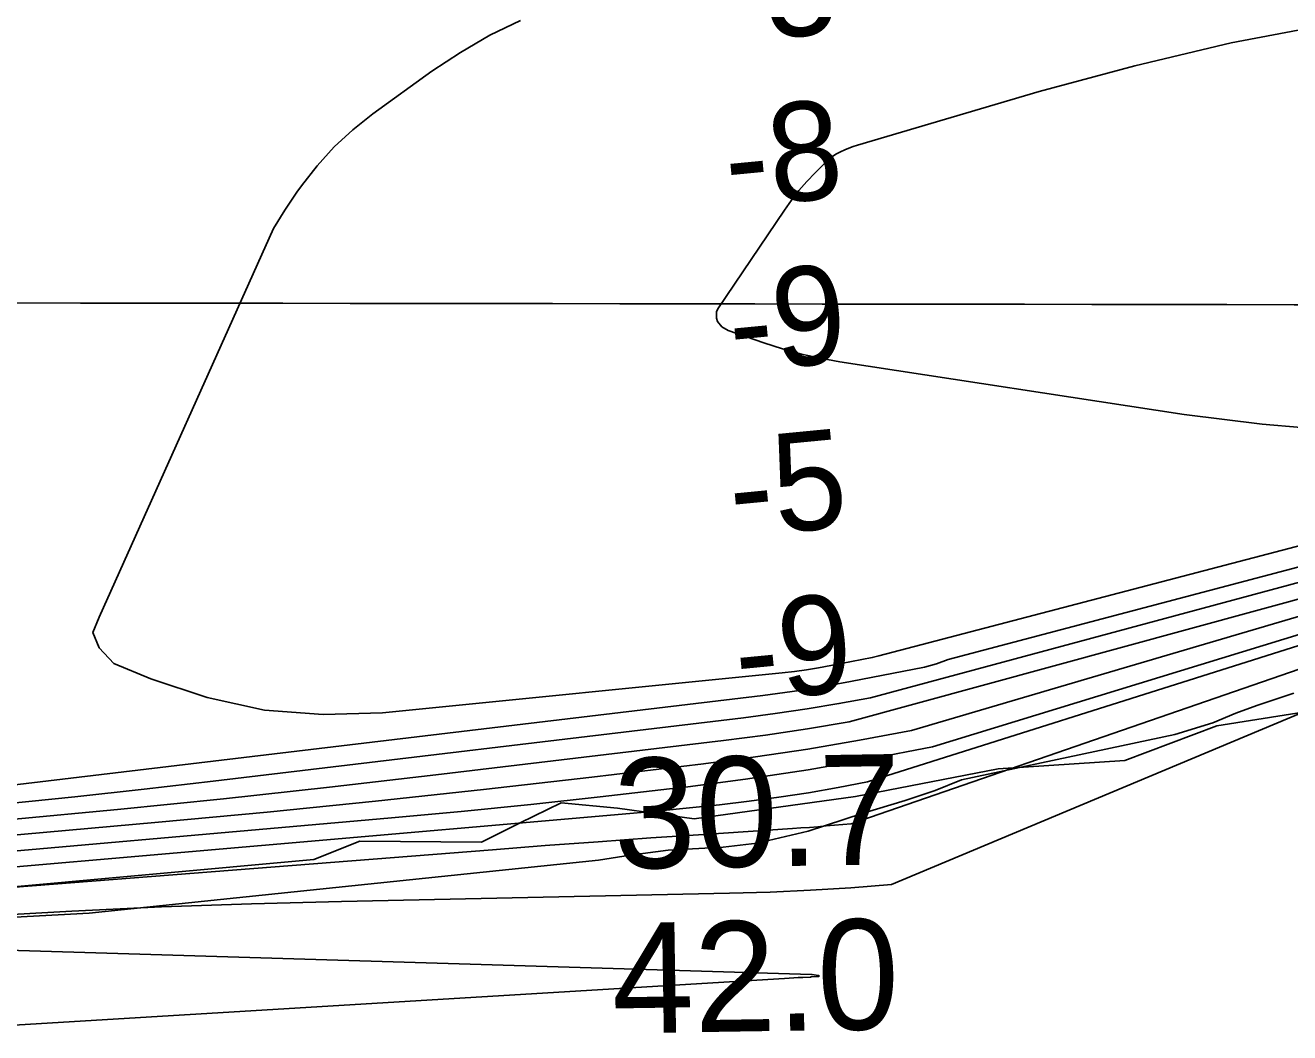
# Model space of a CAD drawing. Extents: x 3219052 to 3256913, y 800770 to 826146.
# Drawn here: x 3230928 to 3231695, y 811791 to 812403 of the extents above; entities that cross this region are included whole.
import ezdxf

# ---------------------------------------------------------------- set-up
doc = ezdxf.new("R2010")
doc.units = 0
for name, color, linetype in [('V-GRID-MAJR', 7, 'Continuous'), ('V-RIVR-EDGE', 7, 'Continuous'), ('V-RIVR-RANG', 7, 'Continuous'), ('V-SITE-VEGE', 7, 'Continuous'), ('V-TOPO-DPTH', 7, 'Continuous'), ('V-TOPO-MAJR', 7, 'Continuous'), ('V-TOPO-MINR', 7, 'Continuous'), ('V-TOPO-WATR', 7, 'Continuous')]:
    doc.layers.add(name, color=color, linetype=linetype)

msp = doc.modelspace()

# ---------------------------------------------------------------- linework, layer by layer
at = {"layer": 'V-GRID-MAJR'}
msp.add_spline([(3223229.222, 812245.659), (3228465.955, 812237.661), (3233702.6890000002, 812230.425), (3238939.4250000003, 812223.951), (3244176.161, 812218.238), (3249412.899, 812213.287), (3254649.637, 812209.098), (3254649.6380000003, 812209.098)], degree=3, dxfattribs=at)
at = {"layer": 'V-RIVR-EDGE'}
msp.add_lwpolyline([(3230903.1019634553, 811878.0231763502), (3231103.0993838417, 811896.2198451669), (3231130.9466271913, 811907.4526457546), (3231204.8405620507, 811906.8352481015), (3231228.3421149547, 811918.5134735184), (3231253.1487722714, 811930.6231509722), (3231287.4806941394, 811927.4955036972), (3231333.9749601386, 811920.8603489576), (3231431.8115734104, 811934.5281610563), (3231518.354120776, 811951.2666544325), (3231595.304764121, 811956.2925278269), (3231650.996026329, 811977.4540994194), (3231716.223301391, 811987.7251115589)], dxfattribs=at)
at = {"layer": 'V-SITE-VEGE'}
for points in [[(3231351.543, 811903.647), (3231372.062, 811906.103), (3231403.021, 811913.412), (3231435.812, 811924.207), (3231461.94, 811932.0530000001), (3231480.108, 811938.074), (3231496.0870000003, 811944.5800000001), (3231625.6180000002, 811972.167), (3231648.648, 811979.194), (3231662.632, 811985.077), (3231675.27, 811989.669), (3231697.87, 811997.1460000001)], [(3230902.756, 811860.164), (3230966.879, 811863.733), (3231275.892, 811895.9010000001), (3231295.1, 811898.824), (3231318.052, 811901.89), (3231351.543, 811903.647)]]:
    msp.add_lwpolyline(points, dxfattribs=at)
at = {"layer": 'V-TOPO-DPTH'}
for points in [[(3231228.470283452, 812405.5174824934), (3231209.8754390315, 812396.6128912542), (3231192.0775494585, 812386.2063975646), (3231174.810963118, 812374.7986355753), (3231138.9305299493, 812348.9006319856), (3231126.8381560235, 812339.2345024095), (3231115.4585998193, 812328.859579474), (3231105.148270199, 812317.4214664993), (3231095.550758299, 812305.2745601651), (3231092.795754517, 812301.4117371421), (3231085.4584558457, 812290.4593476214), (3231078.5657916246, 812279.2511318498), (3230972.842580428, 812043.4696653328), (3230969.0998905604, 812034.0702753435), (3230972.873749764, 812024.6833564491), (3230981.658641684, 812015.3047516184), (3231004.2032776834, 812005.9615947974), (3231038.455751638, 811994.6830115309), (3231073.2217979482, 811986.8883609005), (3231108.7582027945, 811984.3196092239), (3231144.808179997, 811985.2347901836), (3231387.3178908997, 812009.608056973), (3231394.7129821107, 812010.4547092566), (3231402.0880969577, 812011.436995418), (3231409.433247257, 812012.622732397), (3231416.7584211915, 812013.9441032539), (3231441.950385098, 812018.8489342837), (3231445.9223999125, 812019.9308635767), (3231982.116089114, 812160.2718226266)], [(3231228.470283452, 812405.5174824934), (3231209.8754390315, 812396.6128912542), (3231192.0775494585, 812386.2063975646), (3231174.810963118, 812374.7986355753), (3231138.9305299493, 812348.9006319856), (3231126.8381560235, 812339.2345024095), (3231115.4585998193, 812328.859579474), (3231105.148270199, 812317.4214664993), (3231095.550758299, 812305.2745601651), (3231092.795754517, 812301.4117371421), (3231085.4584558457, 812290.4593476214), (3231078.5657916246, 812279.2511318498), (3230972.842580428, 812043.4696653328), (3230969.0998905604, 812034.0702753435), (3230972.873749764, 812024.6833564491), (3230981.658641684, 812015.3047516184), (3231004.2032776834, 812005.9615947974), (3231038.455751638, 811994.6830115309), (3231073.2217979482, 811986.8883609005), (3231108.7582027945, 811984.3196092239), (3231144.808179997, 811985.2347901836), (3231387.3178908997, 812009.608056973), (3231394.7129821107, 812010.4547092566), (3231402.0880969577, 812011.436995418), (3231409.433247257, 812012.622732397), (3231416.7584211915, 812013.9441032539), (3231441.950385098, 812018.8489342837), (3231445.9223999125, 812019.9308635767), (3231982.116089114, 812160.2718226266)], [(3233098.349688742, 812373.6540765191), (3232486.2368681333, 812270.0368842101), (3232472.3644264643, 812267.6833421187), (3232458.5200075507, 812265.1815515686), (3232444.7176227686, 812262.45738833), (3232430.9432607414, 812259.5849766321), (3232002.2757216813, 812145.8369136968), (3231440.9252670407, 811994.4826974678), (3231421.714519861, 811990.9133475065), (3231402.457251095, 811987.6377519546), (3231383.130199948, 811984.8027880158), (3231363.7566272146, 811982.2615784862), (3231042.0572564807, 811943.7967718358), (3231000.117694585, 811938.9610847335), (3230958.1533135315, 811934.360955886), (3230916.1517037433, 811930.1141644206)], [(3230916.1517037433, 811930.1141644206), (3230958.1533135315, 811934.360955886), (3231000.117694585, 811938.9610847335), (3231042.0572564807, 811943.7967718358), (3231363.7566272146, 811982.2615784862), (3231383.130199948, 811984.8027880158), (3231402.457251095, 811987.6377519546), (3231421.714519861, 811990.9133475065), (3231440.9252670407, 811994.4826974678), (3232002.2757216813, 812145.8369136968), (3232430.9432607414, 812259.5849766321), (3232444.7176227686, 812262.45738833), (3232458.5200075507, 812265.1815515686), (3232472.3644264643, 812267.6833421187), (3232486.2368681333, 812270.0368842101), (3233098.349688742, 812373.6540765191)], [(3233156.239928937, 812345.4144281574), (3232562.990278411, 812238.0299150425), (3232553.054541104, 812236.3939197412), (3232543.109941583, 812234.815359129), (3232533.15204874, 812233.3229505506), (3232523.1852936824, 812231.8879766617), (3232513.230339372, 812230.3910913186), (3232503.2999576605, 812228.7543577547), (3232493.4064348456, 812226.90785186), (3232483.537484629, 812224.9214977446), (3232479.2659793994, 812224.0146192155), (3232467.289212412, 812221.4275986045), (3231967.5589998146, 812122.4509561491), (3231465.7381548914, 811974.6738844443), (3231434.3190708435, 811968.7257062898), (3231402.819035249, 811963.2818956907), (3231371.1975723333, 811958.5946364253), (3231339.4951578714, 811954.4117447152), (3231271.806260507, 811946.3050010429), (3231206.167293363, 811938.7475382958), (3231140.4865882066, 811931.5900274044), (3231074.743276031, 811925.0324442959), (3231008.958225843, 811918.8748130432), (3230827.9939512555, 811902.769120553)]]:
    msp.add_lwpolyline(points, dxfattribs=at)
at = {"layer": 'V-TOPO-MAJR'}
msp.add_lwpolyline([(3230859.4972477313, 811874.5255959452), (3231211.463408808, 811902.2274491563), (3231243.5132287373, 811904.6882806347), (3231275.5689604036, 811907.0673374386), (3231307.633559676, 811909.3237322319), (3231339.704070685, 811911.4983523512), (3231393.599473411, 811915.0493001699), (3231398.7255397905, 811915.4026005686), (3231403.850036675, 811915.7765489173), (3231408.9721793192, 811916.1814691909), (3231414.092752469, 811916.6070374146), (3231429.257659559, 811917.9135520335), (3231899.6914986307, 812080.3429716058)], dxfattribs=at)
at = {"layer": 'V-TOPO-MINR'}
for points in [[(3231228.470283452, 812405.5174824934), (3231209.8754390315, 812396.6128912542), (3231192.0775494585, 812386.2063975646), (3231174.810963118, 812374.7986355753), (3231138.9305299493, 812348.9006319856), (3231126.8381560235, 812339.2345024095), (3231115.4585998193, 812328.859579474), (3231105.148270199, 812317.4214664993), (3231095.550758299, 812305.2745601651), (3231092.795754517, 812301.4117371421), (3231085.4584558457, 812290.4593476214), (3231078.5657916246, 812279.2511318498), (3230972.842580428, 812043.4696653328), (3230969.0998905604, 812034.0702753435), (3230972.873749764, 812024.6833564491), (3230981.658641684, 812015.3047516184), (3231004.2032776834, 812005.9615947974), (3231038.455751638, 811994.6830115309), (3231073.2217979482, 811986.8883609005), (3231108.7582027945, 811984.3196092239), (3231144.808179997, 811985.2347901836), (3231387.3178908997, 812009.608056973), (3231394.7129821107, 812010.4547092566), (3231402.0880969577, 812011.436995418), (3231409.433247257, 812012.622732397), (3231416.7584211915, 812013.9441032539), (3231441.950385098, 812018.8489342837), (3231445.9223999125, 812019.9308635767), (3231982.116089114, 812160.2718226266)], [(3231718.7033630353, 812403.1763464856), (3231659.701011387, 812391.9968638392), (3231601.273605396, 812378.1225508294), (3231543.2294965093, 812362.4516842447), (3231433.0033608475, 812329.9596546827), (3231430.38679653, 812329.1151355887), (3231427.8041605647, 812328.1835796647), (3231425.2724171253, 812327.1214684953), (3231422.7746020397, 812325.9723204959), (3231420.3811386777, 812324.6469930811), (3231418.0903942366, 812323.1775266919), (3231415.9537281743, 812321.4918518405), (3231413.9197810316, 812319.6620380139), (3231407.3636469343, 812313.155780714), (3231402.299349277, 812307.8227287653), (3231397.4585169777, 812302.3050451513), (3231392.952882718, 812296.5104140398), (3231388.6707138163, 812290.5311512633), (3231348.361560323, 812230.5666397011), (3231347.5272323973, 812228.6839642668), (3231347.376836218, 812224.8589172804), (3231348.0607679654, 812222.9165457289), (3231350.794592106, 812219.6260277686), (3231354.5123948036, 812217.5096048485), (3231376.1061868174, 812209.9317489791), (3231387.488627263, 812206.2909091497), (3231398.9784752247, 812203.0804262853), (3231410.629434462, 812200.5154788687), (3231422.3878012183, 812198.3808884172), (3231631.2095695, 812166.4655886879), (3231678.5091910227, 812160.6020928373), (3231725.911758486, 812156.5301610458)], [(3230909.7779353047, 811940.1000302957), (3231375.6213572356, 811995.8697754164), (3231388.9645777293, 811997.6184653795), (3231402.276629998, 811999.5648836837), (3231415.541929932, 812001.8078944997), (3231428.77606164, 812004.2486336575), (3231473.592392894, 812013.0323078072), (3231480.9644786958, 812015.0252567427), (3231488.0453462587, 812017.6596658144), (3232013.5471657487, 812156.589880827), (3232045.6238793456, 812162.8151654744), (3232436.2519301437, 812280.2505831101), (3232459.941382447, 812285.0879870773), (3232483.706498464, 812289.5388171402), (3232507.5220569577, 812293.7319312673), (3232584.6246720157, 812306.660394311), (3233085.958948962, 812387.211552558)], [(3230919.4482350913, 811920.5737085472), (3230983.92161747, 811926.6673520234), (3231048.3556352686, 811933.136541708), (3231112.7306061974, 811940.169050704), (3231177.066212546, 811947.577105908), (3231351.7311122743, 811968.4636540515), (3231377.2160688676, 811971.8138223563), (3231402.6380203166, 811975.5594926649), (3231427.965464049, 811979.8984159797), (3231964.852140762, 812126.4828974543), (3232416.4774682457, 812236.7248742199), (3232423.5506967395, 812238.8422121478), (3232430.7014445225, 812240.6808223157), (3232437.9038718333, 812242.3336139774), (3232448.4340848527, 812244.5336939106), (3232452.7988938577, 812245.4096572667), (3232457.1720889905, 812246.2394308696), (3232461.557863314, 812246.9999198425), (3232465.9520237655, 812247.7142190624), (3233157.50439058, 812360.4364484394)], [(3230827.9939512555, 811902.769120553), (3231008.958225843, 811918.8748130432), (3231074.743276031, 811925.0324442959), (3231140.4865882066, 811931.5900274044), (3231206.167293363, 811938.7475382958), (3231271.806260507, 811946.3050010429), (3231339.4951578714, 811954.4117447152), (3231371.1975723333, 811958.5946364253), (3231402.819035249, 811963.2818956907), (3231434.3190708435, 811968.7257062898), (3231465.7381548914, 811974.6738844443), (3231967.5589998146, 812122.4509561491), (3232467.289212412, 812221.4275986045), (3232479.2659793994, 812224.0146192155), (3232483.537484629, 812224.9214977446), (3232493.4064348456, 812226.90785186), (3232503.2999576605, 812228.7543577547), (3232513.230339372, 812230.3910913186), (3232523.1852936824, 812231.8879766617), (3232533.15204874, 812233.3229505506), (3232543.109941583, 812234.815359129), (3232553.054541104, 812236.3939197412), (3232562.990278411, 812238.0299150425), (3233156.239928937, 812345.4144281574)], [(3230837.8612534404, 811894.0736250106), (3231150.298528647, 811921.5222196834), (3231192.530069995, 811925.4368195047), (3231234.7335255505, 811929.6214623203), (3231276.8948524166, 811934.2111696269), (3231319.0280934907, 811939.0709199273), (3231326.9945756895, 811940.02857483), (3231365.047873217, 811945.0788177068), (3231403.0004671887, 811950.7505149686), (3231440.802005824, 811957.3543938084), (3231478.5028409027, 811964.5797270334), (3231952.4298236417, 812110.0529328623), (3232115.7254834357, 812133.6460863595), (3232172.2098851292, 812142.1591000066), (3232228.6185235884, 812151.1304446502), (3232400.1222106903, 812181.8940793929), (3232426.813538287, 812186.7205580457), (3232453.5364188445, 812191.359418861), (3232480.306628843, 812195.7168529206), (3232507.1083918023, 812199.8866691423), (3232543.7690222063, 812205.3929408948), (3232568.7269474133, 812209.2154199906), (3233147.483664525, 812329.3229014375)], [(3230847.7329094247, 811885.3534478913), (3231294.9250262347, 811924.1199622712), (3231313.052071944, 811925.7842809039), (3231331.1663779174, 811927.5713430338), (3231349.261574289, 811929.5425204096), (3231367.3440309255, 811931.636441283), (3231385.379596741, 811934.0500581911), (3231403.365458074, 811936.7667134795), (3231421.2767626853, 811939.9379263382), (3231439.138362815, 811943.4121775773), (3231915.2320351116, 812093.9400519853), (3231928.4322151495, 812095.8886727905), (3231941.6378416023, 812097.8009196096), (3232201.8475326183, 812134.9316493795), (3232243.577777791, 812140.9298019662), (3232285.2997304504, 812146.9846879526), (3232327.0092443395, 812153.1246740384), (3232368.710465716, 812159.321393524), (3232418.298707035, 812166.7418134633), (3232435.2132132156, 812169.1647334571), (3232452.1458793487, 812171.4461848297), (3232469.105785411, 812173.5154332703), (3232486.083851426, 812175.4432130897), (3233153.0441230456, 812306.1480581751)], [(3230901.7195805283, 811861.8730827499), (3230956.217591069, 811864.8834972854), (3231010.7336626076, 811867.4545391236), (3231065.2768256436, 811869.3665219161), (3231119.8380496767, 811870.8391320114), (3231355.355647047, 811875.7716186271), (3231379.940414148, 811876.5264303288), (3231404.508102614, 811877.6005076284), (3231429.050173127, 811879.1534833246), (3231453.575165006, 811881.025724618), (3231901.5528504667, 812068.6036280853)], [(3230863.619341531, 811842.9126494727), (3231405.1078231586, 811826.3766520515), (3231405.453716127, 811826.3640227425), (3231406.724473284, 811826.2968960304), (3231409.223214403, 811825.894196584), (3231409.6179768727, 811825.7869904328), (3231409.767565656, 811825.6328461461), (3231409.823797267, 811825.4880418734)], [(3231409.823797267, 811825.4880418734), (3231409.739993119, 811825.3572476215), (3231409.5628317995, 811825.2357933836), (3231404.952970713, 811824.9406245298), (3231404.4271117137, 811824.9121759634), (3231399.900542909, 811824.6766651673), (3231397.111534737, 811824.5280067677), (3231394.3227921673, 811824.3746284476), (3231391.5344479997, 811824.2141702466), (3231388.746369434, 811824.0489921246), (3230844.2406326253, 811791.0963533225)]]:
    msp.add_lwpolyline(points, dxfattribs=at)
at = {"layer": 'V-TOPO-WATR'}
msp.add_lwpolyline([(3230916.1517037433, 811930.1141644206), (3230958.1533135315, 811934.360955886), (3231000.117694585, 811938.9610847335), (3231042.0572564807, 811943.7967718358), (3231363.7566272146, 811982.2615784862), (3231383.130199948, 811984.8027880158), (3231402.457251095, 811987.6377519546), (3231421.714519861, 811990.9133475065), (3231440.9252670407, 811994.4826974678), (3232002.2757216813, 812145.8369136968), (3232430.9432607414, 812259.5849766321), (3232444.7176227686, 812262.45738833), (3232458.5200075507, 812265.1815515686), (3232472.3644264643, 812267.6833421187), (3232486.2368681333, 812270.0368842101), (3233098.349688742, 812373.6540765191)], dxfattribs=at)

# ---------------------------------------------------------------- texts
at = {"layer": 'V-RIVR-RANG'}
for s, height, rotation, p in [('-5', 59.99999999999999, 5.505138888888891, (3231352.178781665, 812391.684641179)), ('-8', 59.99999999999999, 5.505138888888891, (3231354.91630538, 812291.7912884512)), ('-9', 59.99999999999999, 5.505138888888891, (3231357.418698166, 812191.8762739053)), ('-5', 59.99999999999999, 5.505138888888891, (3231357.5697816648, 812091.733641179)), ('-9', 59.99999999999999, 5.505138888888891, (3231361.0126981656, 811991.9082739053)), ('30.7', 67, 0.8883257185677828, (3231285.49884917, 811890.6647382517)), ('42.0', 67, 0.8883257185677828, (3231284.3946231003, 811790.6357534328))]:
    msp.add_text(s, height=height, rotation=rotation, dxfattribs=at).set_placement(p)

doc.saveas('drawing.dxf')
